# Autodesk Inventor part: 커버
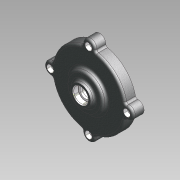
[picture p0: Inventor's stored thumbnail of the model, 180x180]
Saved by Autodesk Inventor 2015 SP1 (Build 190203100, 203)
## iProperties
Company: 한국ATC센터
Created: 2014-07
Part Number: 커버
Document SubType Name: 모델링
Designer: KYOUNG IL JANG
Material: 알루미늄 6061
Appearance: 알루미늄 캐스트
Mass: 195.931 g
Surface Area: 278.607 cm^2
Volume: 72.5671 cm^3
Density: 2.7 g/cm^3
변환 표준: STEP AP214IS
파일 이름: C:\Users\SeoGD\Desktop\?쒗뿕\而ㅻ쾭-1.stp
전처리기: Build: 253, Release: 2010 SP1 - Date: Wed 07/29/2009
전송 단위: 밀리미터
불확실성: 0.01
Author: KYOUNG IL JANG
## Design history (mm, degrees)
sketch "스케치1"
  geometry: L1 (0, 0)-(0, 26); L2 (50, 0)-(50, 15); L3 (50, 15)-(25, 15); L4 (25, 15)-(25, 21); L5 (25, 21)-(15, 21); L6 (15, 21)-(13.66, 26); L7 (13.66, 26)-(10, 26); L8 (50, 0)-(45, 0); L9 (45, 0)-(45, 10); L10 (45, 10)-(14.5, 10); L11 (14.5, 10)-(13.266, 3); L12 (13.266, 3)-(11, 3); L13 (11, 3)-(11, 16); L14 (11, 16)-(7.5, 16); L15 (7.5, 16)-(7.5, 19); L16 (7.5, 19)-(10, 19); L17 (10, 19)-(10, 26)
  constraints: 34 end point, 10 parallel, 2 perpendicular, 2 point on line, 1 vertical
  dimensions: "d11" = 100 diameter of L2 L1; "d12" = 22 diameter of L13 L1; "d13" = 90 diameter of L9 L1; "d14" = 15 distance between parallel lines of L3 L8; "d15" = 10 distance between parallel lines of L8 L10; "d16" = 29 diameter of L10.end L1; "d17" = 100 deg angle of L11 L10; "d18" = 7 distance between parallel lines of L12 L10; "d19" = 13 distance between parallel lines of L14 L12; "d20" = 3 distance between parallel lines of L16 L14; "d21" = 15 diameter of L15 L1; "d22" = 20 diameter of L17 L1; "d23" = 30 diameter of L5.end L1; "d24" = 6 distance between parallel lines of L5 L3; "d25" = 50 diameter of L4 L1; "d26" = 105 deg angle of L5 L6; "d50" = 26 distance of L1.start L1.end
revolve "회전1" sketch "스케치1" stored, may be unused: angle "d27" = 90 deg
sketch "스케치2" dims "d29" = 104
  geometry: A1 r 8.5 centre (0, 52) between (8.074, 49.344) and (-8.074, 49.344); A2 r 50 centre (0, 0) between (-8.074, 49.344) and (8.074, 49.344) reference; 2 further points
  constraints: 4 point on circle, 2 vertical alignment, 1 centre point, 1 coincident, 2 other
  dimensions: "d28" = 17 diameter of A1
extrude "돌출1" join sketch "스케치2" stored distance "d30" = 10; taper "d31" = 0 deg
fillet "모깎기3" dims "d32" = 3
fillet "모깎기4" dims "d45" = 3, "d46" = 0.2
chamfer "모따기1" distance "d47" = 1; stored, may be unused: second distance "d48" = 2, angle "d49" = 45 deg
hole "구멍2" diameter "d38" = 5.5; stored, may be unused: countersink angle "d42" = 90 deg, drill point angle "d44" = 118 deg; dims "d36" = 10, "d37" = 10, "d39" = 6, "d40" = 9.5, "d41" = 5.4, "d43" = 8
node "솔리드1"
node "솔리드 본체"
node "곡면 본체"
pattern_circular "원형 패턴1" dims angle "d34" = 360 deg
pattern_circular "원형 패턴2" dims angle "d52" = 360 deg
node "솔리드2"
